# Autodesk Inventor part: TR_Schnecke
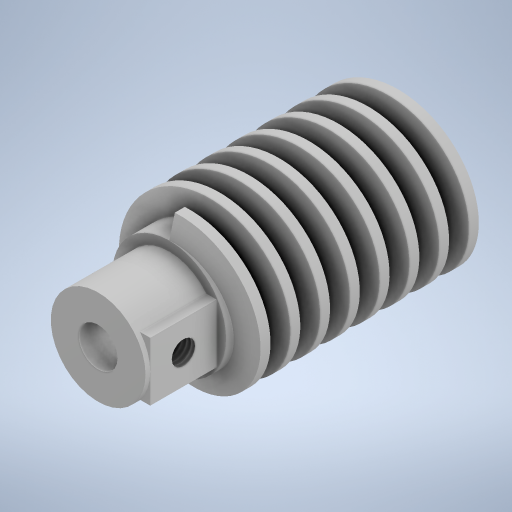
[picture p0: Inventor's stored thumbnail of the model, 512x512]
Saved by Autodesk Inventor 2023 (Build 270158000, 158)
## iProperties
Created: 2023-11
Part Number: TR_Schnecke
Material: PC/ABS-Kunststoff
Document SubType Name: Modeling
Designer: AdminForWorker
Density: 0.357273 g/cm^3
Appearance: Glatt - Marine
Title: Component2
Author: AdminForWorker
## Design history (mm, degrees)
feature "Body1"
sketch "Skizze1"
  geometry: C1 r 5 at (0, 0); 1 further point
  constraints: 1 centre point, 1 coincident
  dimensions: "d0" = 10 diameter of C1
extrude "Extrusion1" join sketch "Skizze1" distance "d1" = 7.5; taper "d2" = 0 deg
sketch "Skizze2"
  geometry: L1 (3.1, 25)-(-3.1, 25); L2 (-3.1, 25)-(-3.1, 32); L3 (-3.1, 32)-(3.1, 32); L4 (3.1, 32)-(3.1, 25); L5 (6, 25)-(-6, 25) reference; 2 further points
  constraints: 8 end point, 2 parallel, 1 horizontal, 1 midpoint, 1 perpendicular, 1 point on line, 1 vertical alignment
  dimensions: "d3" = 7 distance of L3.end L1.start; "d4" = 6.2 distance of L2.end L3.end
extrude "Extrusion2" join sketch "Skizze2" distance "d5" = 5; taper "d6" = 0 deg
sketch "Skizze3"
  geometry: L1 (-25, 3.1)-(-32, 3.1) reference; 4 further points
  constraints: 1 horizontal alignment, 1 midpoint, 1 vertical alignment
hole "Bohrung1" sketch "Skizze3" at (-28.5, 0) diameter "d7" = 2.459; stored, may be unused: countersink angle "d11" = 90 deg, drill point angle "d13" = 0 deg; dims "d8" = 5, "d9" = 4, "d10" = 2, "d12" = 5
sketch "Skizze4"
  geometry: C1 r 2.05 at (0, 0); 1 further point
  constraints: 1 centre point, 1 coincident
  dimensions: "d14" = 4.1 diameter of C1 (= DAchsAufnahme)
extrude "Extrusion3" cut sketch "Skizze4" extent not by distance; stored distance "d15" = 0; taper "d16" = 0 deg
body "Solid1"
other parameters: "Radius" = 2.075 [user parameter], "Fasen" = 0.5 [user parameter], "Dicke" = 0.8 [user parameter], "Breitloch" = 2 [user parameter], "Langloch" = 32 [user parameter], "AchteckUmkreis" = 6 [user parameter], "DAchsAufnahme" = 4.1 [user parameter; used in 1 equation term], "AchsDurchmesser" = 4 [user parameter], "AchsFase" = 0.5 [user parameter]
